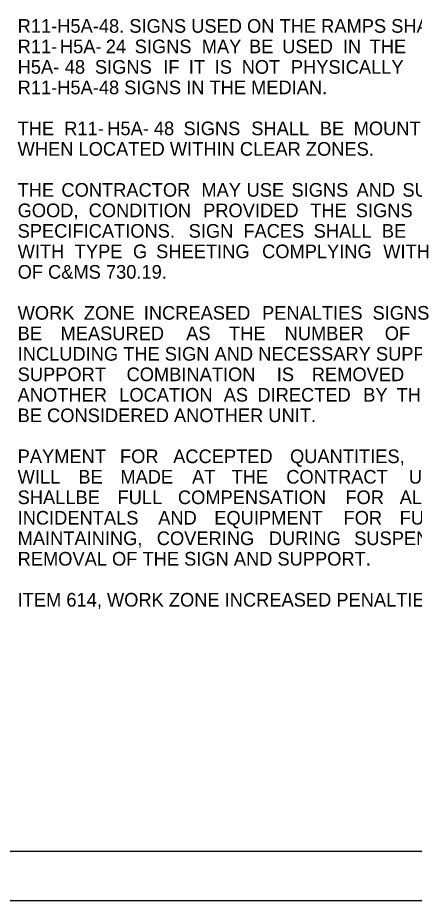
# Model space of a CAD drawing. Extents: x 0 to 43.6, y -18 to 22.
# Drawn here: x 24.66 to 28.73, y 0 to 9.04 of the extents above; entities that cross this region are included whole.
import ezdxf

# ---------------------------------------------------------------- set-up
doc = ezdxf.new("R2010")
doc.units = 0
for name, color, linetype in [('SH_Border', 7, 'Continuous'), ('SH_Cut_Line', 7, 'Continuous'), ('SH_Text', 7, 'Continuous')]:
    doc.layers.add(name, color=color, linetype=linetype)

msp = doc.modelspace()

# ---------------------------------------------------------------- linework, layer by layer
at = {"layer": 'SH_Border'}
msp.add_lwpolyline([(1.5, 21.5), (33.5, 21.5), (33.5, 0.5), (1.5, 0.5)], close=True, dxfattribs=at)
at = {"layer": 'SH_Cut_Line'}
msp.add_lwpolyline([(0, 0), (34, 0), (34, 22), (0, 22)], close=True, dxfattribs=at)

# ---------------------------------------------------------------- texts
at = {"layer": 'SH_Text'}
for s, p in [('R11-H5A-48. SIGNS USED ON THE RAMPS SHALL BE R11-H5A-24.', (24.66, 8.89)), ('R11-', (24.66, 8.68)), ('H5A-', (25.0937, 8.68)), ('24 ', (25.5636, 8.68)), ('SIGNS ', (25.8597, 8.68)), ('MAY ', (26.5471, 8.68)), ('BE ', (27.0316, 8.68)), ('USED ', (27.3713, 8.68)), ('IN ', (27.9935, 8.68)), ('THE ', (28.2677, 8.68)), ('H5A-', (24.66, 8.47)), ('48 ', (25.1429, 8.47)), ('SIGNS ', (25.452, 8.47)), ('IF ', (26.1523, 8.47)), ('IT ', (26.4142, 8.47)), ('IS ', (26.6797, 8.47)), ('NOT ', (26.9561, 8.47)), ('PHYSICALLY ', (27.4606, 8.47)), ('R11-H5A-48 SIGNS IN THE MEDIAN.', (24.66, 8.26)), ('THE ', (24.66, 7.84)), ('R11-', (25.1374, 7.84)), ('H5A-', (25.5785, 7.84)), ('48 ', (26.056, 7.84)), ('SIGNS ', (26.3595, 7.84)), ('SHALL ', (27.0544, 7.84)), ('BE ', (27.7568, 7.84)), ('MOUNTED ', (28.1039, 7.84)), ('WHEN LOCATED WITHIN CLEAR ZONES.', (24.66, 7.63)), ('THE ', (24.66, 7.21)), ('CONTRACTOR ', (25.1089, 7.21)), ('MAY ', (26.5433, 7.21)), ('USE ', (27.0068, 7.21)), ('SIGNS ', (27.4667, 7.21)), ('AND ', (28.1331, 7.21)), ('SUPPORTS ', (28.6037, 7.21)), ('GOOD, ', (24.66, 7)), ('CONDITION ', (25.3878, 7)), ('PROVIDED ', (26.5612, 7)), ('THE ', (27.6588, 7)), ('SIGNS ', (28.1258, 7)), ('SPECIFICATIONS. ', (24.66, 6.79)), ('SIGN ', (26.4129, 6.79)), ('FACES ', (26.9737, 6.79)), ('SHALL ', (27.6941, 6.79)), ('BE ', (28.393, 6.79)), ('WITH ', (24.66, 6.58)), ('TYPE ', (25.2453, 6.58)), ('G ', (25.842, 6.58)), ('SHEETING ', (26.0797, 6.58)), ('COMPLYING ', (27.1654, 6.58)), ('WITH ', (28.407, 6.58)), ('OF C&MS 730.19.', (24.66, 6.37)), ('WORK ', (24.66, 5.95)), ('ZONE ', (25.339, 5.95)), ('INCREASED ', (25.953, 5.95)), ('PENALTIES ', (27.1649, 5.95)), ('SIGNS ', (28.2972, 5.95)), ('BE ', (24.66, 5.74)), ('MEASURED ', (25.0996, 5.74)), ('AS ', (26.387, 5.74)), ('THE ', (26.8266, 5.74)), ('NUMBER ', (27.3964, 5.74)), ('OF ', (28.4228, 5.74)), ('INCLUDING THE SIGN AND NECESSARY SUPPORTS. IF A SIGN AND', (24.66, 5.53)), ('SUPPORT ', (24.66, 5.32)), ('COMBINATION ', (25.7763, 5.32)), ('IS ', (27.316, 5.32)), ('REMOVED ', (27.6749, 5.32)), ('ANOTHER ', (24.66, 5.11)), ('LOCATION ', (25.7013, 5.11)), ('AS ', (26.7715, 5.11)), ('DIRECTED ', (27.1173, 5.11)), ('BY ', (28.202, 5.11)), ('THE ', (28.5443, 5.11)), ('BE CONSIDERED ANOTHER UNIT.', (24.66, 4.9)), ('PAYMENT ', (24.66, 4.48)), ('FOR ', (25.709, 4.48)), ('ACCEPTED ', (26.2542, 4.48)), ('QUANTITIES, ', (27.4519, 4.48)), ('WILL ', (24.66, 4.27)), ('BE ', (25.2824, 4.27)), ('MADE ', (25.7129, 4.27)), ('AT ', (26.4476, 4.27)), ('THE ', (26.8526, 4.27)), ('CONTRACT ', (27.4134, 4.27)), ('UNIT ', (28.6698, 4.27)), ('SHALLBE ', (24.66, 4.06)), ('FULL ', (25.6844, 4.06)), ('COMPENSATION ', (26.3029, 4.06)), ('FOR ', (28.019, 4.06)), ('ALL ', (28.5756, 4.06)), ('INCIDENTALS ', (24.66, 3.85)), ('AND ', (26.1008, 3.85)), ('EQUIPMENT ', (26.6756, 3.85)), ('FOR ', (28.0004, 3.85)), ('FURNISHING, ', (28.5751, 3.85)), ('MAINTAINING, ', (24.66, 3.64)), ('COVERING ', (26.0862, 3.64)), ('DURING ', (27.2337, 3.64)), ('SUSPENSION ', (28.1093, 3.64)), ('REMOVAL OF THE SIGN AND SUPPORT.', (24.66, 3.43)), ('ITEM 614, WORK ZONE INCREASED PENALTIES SIGN         20 EACH', (24.66, 3.01))]:
    msp.add_text(s, height=0.14, dxfattribs=at).set_placement(p)

doc.saveas('drawing.dxf')
